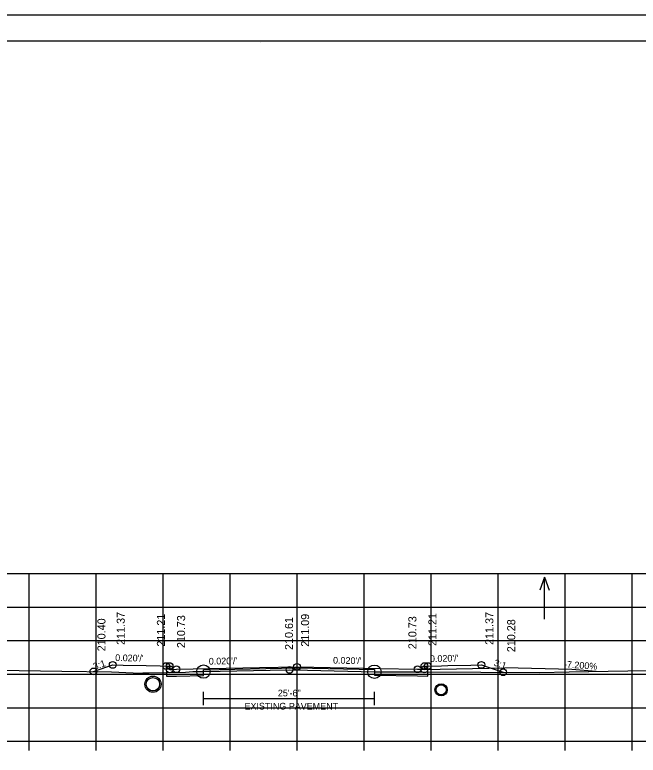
# Model space of a CAD drawing. Extents: x 1368968 to 1369915, y 377395 to 380381.
# Drawn here: x 1369096 to 1369189.1, y 378150.6 to 378261 of the extents above; entities that cross this region are included whole.
import ezdxf

# ---------------------------------------------------------------- set-up
doc = ezdxf.new("R2010")
doc.units = 0
for name, color, linetype in [('Default', 7, 'Continuous'), ('S_BORDER_NO_PLOT', 7, 'Continuous'), ('S_BREAKLINE_ANNOT', 7, 'Continuous'), ('S_BRIDGE_ANNOT', 7, 'Continuous'), ('S_CROSS_DRAIN', 7, 'Continuous'), ('S_CTL_TABLE', 7, 'Continuous'), ('S_CURB_ANNOT', 7, 'Continuous'), ('S_DITCHLINE_ANNOT', 7, 'Continuous'), ('S_DROP_INLET', 7, 'Continuous'), ('S_EXIST_ROW_ANNOT', 7, 'Continuous'), ('S_EXISTING_ALIGNMENT', 7, 'Continuous'), ('S_EXISTING_ALIGNMENT_ANNOT', 7, 'Continuous'), ('S_FENCE', 7, 'Continuous')]:
    doc.layers.add(name, color=color, linetype=linetype)

msp = doc.modelspace()

# ---------------------------------------------------------------- linework, layer by layer
at = {"layer": 'Default'}
msp.add_line((1369149.68, 378163.38), (1369149.68, 378162.55), dxfattribs=at)
at = {"layer": 'S_BORDER_NO_PLOT'}
msp.add_lwpolyline([(1369118.62, 378163.9), (1369118.63, 378162.38), (1369120.13, 378162.41), (1369124.16, 378162.49), (1369124.16, 378163.33), (1369138.13, 378163.61), (1369149.68, 378163.38), (1369149.68, 378162.55), (1369156.13, 378162.42), (1369157.63, 378162.39), (1369157.64, 378163.9)], dxfattribs=at)
at = {"layer": 'S_BREAKLINE_ANNOT'}
for p, q in [((1368998.13, 378152.69), (1369278.13, 378152.69)), ((1369098.13, 378151.29), (1369098.13, 378152.69)), ((1369108.13, 378151.29), (1369108.13, 378152.69)), ((1369118.13, 378151.29), (1369118.13, 378152.69)), ((1369128.13, 378151.29), (1369128.13, 378152.69)), ((1369138.13, 378151.29), (1369138.13, 378152.69)), ((1369148.13, 378151.29), (1369148.13, 378152.69)), ((1369158.13, 378151.29), (1369158.13, 378152.69)), ((1369168.13, 378151.29), (1369168.13, 378152.69)), ((1369178.13, 378151.29), (1369178.13, 378152.69)), ((1369188.13, 378151.29), (1369188.13, 378152.69))]:
    msp.add_line(p, q, dxfattribs=at)
at = {"layer": 'S_BRIDGE_ANNOT'}
for p, q in [((1368980.13, 378257.15), (1369296.31, 378257.15)), ((1369132.65, 378256.89), (1369132.65, 378256.89)), ((1369132.65, 378256.89), (1369132.65, 378256.89))]:
    msp.add_line(p, q, dxfattribs=at)
at = {"layer": 'S_CROSS_DRAIN'}
for p, q in [((1369157.13, 378163.4), (1369169.13, 378163.64)), ((1369179.13, 378163.38), (1369169.13, 378163.64)), ((1369182.79, 378163.11), (1369179.13, 378163.38)), ((1369124.16, 378159.07), (1369149.68, 378159.07))]:
    msp.add_line(p, q, dxfattribs=at)
at = {"layer": 'S_CTL_TABLE'}
msp.add_lwpolyline([(1369093.45, 378163.28), (1369103.02, 378163.15), (1369110.44, 378163.06), (1369113.7, 378162.91), (1369114.03, 378162.83), (1369114.18, 378162.85), (1369114.68, 378162.84), (1369115.1, 378162.87), (1369116.06, 378162.88), (1369121.5, 378162.99), (1369122.56, 378163.08), (1369123.88, 378163.1), (1369124.16, 378163.07), (1369134.13, 378163.27), (1369137, 378163.32), (1369139.68, 378163.27), (1369149.68, 378163.05), (1369156.8, 378163.05), (1369174.3, 378162.94), (1369178.76, 378163.06), (1369205.02, 378163.48)], dxfattribs=at)
at = {"layer": 'S_CURB_ANNOT'}
msp.add_lwpolyline([(1369107.74, 378163.1), (1369109.77, 378163.77), (1369110.62, 378164.06), (1369112.19, 378164.03), (1369115.62, 378163.96), (1369117.69, 378163.92), (1369118.62, 378163.9), (1369118.97, 378163.9), (1369119.12, 378163.9), (1369119.13, 378163.55), (1369119.13, 378163.4), (1369119.45, 378163.4), (1369120.13, 378163.42), (1369132.51, 378163.66), (1369138.13, 378163.78), (1369150.51, 378163.53), (1369156.13, 378163.42), (1369156.45, 378163.41), (1369157.13, 378163.4), (1369157.14, 378163.55), (1369157.14, 378163.9), (1369157.49, 378163.9), (1369157.64, 378163.9), (1369159.71, 378163.94), (1369160.64, 378163.96), (1369164.08, 378164.03), (1369165.64, 378164.06), (1369166.65, 378163.72), (1369168.9, 378162.97)], dxfattribs=at)
at = {"layer": 'S_DITCHLINE_ANNOT'}
for p, q in [((1368998.13, 378177.69), (1369278.13, 378177.69)), ((1369098.13, 378152.69), (1369098.13, 378177.69)), ((1369108.13, 378152.69), (1369108.13, 378177.69)), ((1369118.13, 378152.69), (1369118.13, 378177.69)), ((1369128.13, 378152.69), (1369128.13, 378177.69)), ((1369138.13, 378152.69), (1369138.13, 378177.69)), ((1369148.13, 378152.69), (1369148.13, 378177.69)), ((1369158.13, 378152.69), (1369158.13, 378177.69)), ((1369168.13, 378152.69), (1369168.13, 378177.69)), ((1369178.13, 378152.69), (1369178.13, 378177.69)), ((1369188.13, 378152.69), (1369188.13, 378177.69)), ((1368998.13, 378172.69), (1369278.13, 378172.69)), ((1368998.13, 378167.69), (1369278.13, 378167.69)), ((1368998.13, 378162.69), (1369278.13, 378162.69)), ((1368998.13, 378157.69), (1369278.13, 378157.69)), ((1368998.13, 378152.69), (1369278.13, 378152.69))]:
    msp.add_line(p, q, dxfattribs=at)
at = {"layer": 'S_DROP_INLET'}
msp.add_line((1368967.73, 378261.05), (1369301.07, 378261.05), dxfattribs=at)
for points in [[(1368967.73, 378261.05), (1369301.07, 378261.05), (1369301.07, 378047.71), (1368967.73, 378047.71)], [(1369214.05, 378257.15), (1369214.05, 378247.27), (1369249.79, 378247.27), (1369249.79, 378244.35), (1369272.99, 378244.35), (1369272.99, 378220.02), (1369296.31, 378220.02), (1369296.31, 378051.69), (1368980.13, 378051.69), (1368980.13, 378257.15)]]:
    msp.add_lwpolyline(points, close=True, dxfattribs=at)
for centre, radius in [((1369110.62, 378164.06), 0.5), ((1369118.62, 378163.9), 0.5), ((1369119.12, 378163.9), 0.5), ((1369157.14, 378163.9), 0.5), ((1369157.64, 378163.9), 0.5), ((1369165.64, 378164.06), 0.5), ((1369107.74, 378163.1), 0.5), ((1369119.13, 378163.4), 0.5), ((1369120.13, 378163.42), 0.5), ((1369120.13, 378163.42), 0.5), ((1369124.16, 378163.07), 1), ((1369137, 378163.32), 0.5), ((1369138.13, 378163.78), 0.5), ((1369149.68, 378163.05), 1), ((1369156.13, 378163.42), 0.5), ((1369156.13, 378163.42), 0.5), ((1369157.13, 378163.4), 0.5), ((1369168.9, 378162.97), 0.5), ((1369116.63, 378161.19), 1.21), ((1369159.63, 378160.35), 0.917)]:
    msp.add_circle(centre, radius, dxfattribs=at)
at = {"layer": 'S_EXIST_ROW_ANNOT'}
for p, q in [((1369124.16, 378158.07), (1369124.16, 378160.07)), ((1369149.68, 378158.07), (1369149.68, 378160.07))]:
    msp.add_line(p, q, dxfattribs=at)
for centre, radius in [((1369116.63, 378161.19), 1), ((1369159.63, 378160.35), 0.75)]:
    msp.add_circle(centre, radius, dxfattribs=at)
at = {"layer": 'S_EXISTING_ALIGNMENT'}
for p, q in [((1369175.05, 378177.16), (1369174.35, 378175.24)), ((1369175.05, 378170.88), (1369175.05, 378177.16)), ((1369175.05, 378177.16), (1369175.75, 378175.24))]:
    msp.add_line(p, q, dxfattribs=at)
at = {"layer": 'S_EXISTING_ALIGNMENT_ANNOT'}
msp.add_line((1369138.13, 378163.3), (1369138.13, 378173.3), dxfattribs=at)

# ---------------------------------------------------------------- texts
at = {"layer": 'S_CROSS_DRAIN'}
msp.add_text('-7.200%', height=1, rotation=355.8818, dxfattribs=at).set_placement((1369177.94, 378163.69))
at = {"layer": 'S_EXIST_ROW_ANNOT'}
for s, p in [('25\'-6"', (1369135.27, 378159.37)), ('EXISTING PAVEMENT', (1369130.29, 378157.41))]:
    msp.add_text(s, height=1, dxfattribs=at).set_placement(p)
at = {"layer": 'S_EXISTING_ALIGNMENT_ANNOT'}
for s, p in [('211.37', (1369112.42, 378167.06)), ('211.21', (1369118.42, 378166.8)), ('210.73', (1369121.43, 378166.58)), ('210.61', (1369137.53, 378166.3)), ('211.09', (1369139.93, 378166.78)), ('210.73', (1369155.95, 378166.42)), ('211.21', (1369158.94, 378166.9)), ('211.37', (1369167.44, 378167.06)), ('210.40', (1369109.54, 378166.1)), ('210.28', (1369170.7, 378165.97))]:
    msp.add_text(s, height=1.2, rotation=90, dxfattribs=at).set_placement(p)
at = {"layer": 'S_FENCE'}
for s, rotation, p in [("0.020'/'", 358.8542, (1369110.99, 378164.65)), ("0.020'/'", 1.1458, (1369157.98, 378164.5)), ('3:1', 18.4324, (1369107.9, 378163.33)), ("0.020'/'", 1.1458, (1369124.97, 378164.11)), ("0.020'/'", 358.8543, (1369143.5, 378164.27)), ('3:1', 341.568, (1369167.43, 378163.99))]:
    msp.add_text(s, height=1, rotation=rotation, dxfattribs=at).set_placement(p)

doc.saveas('drawing.dxf')
